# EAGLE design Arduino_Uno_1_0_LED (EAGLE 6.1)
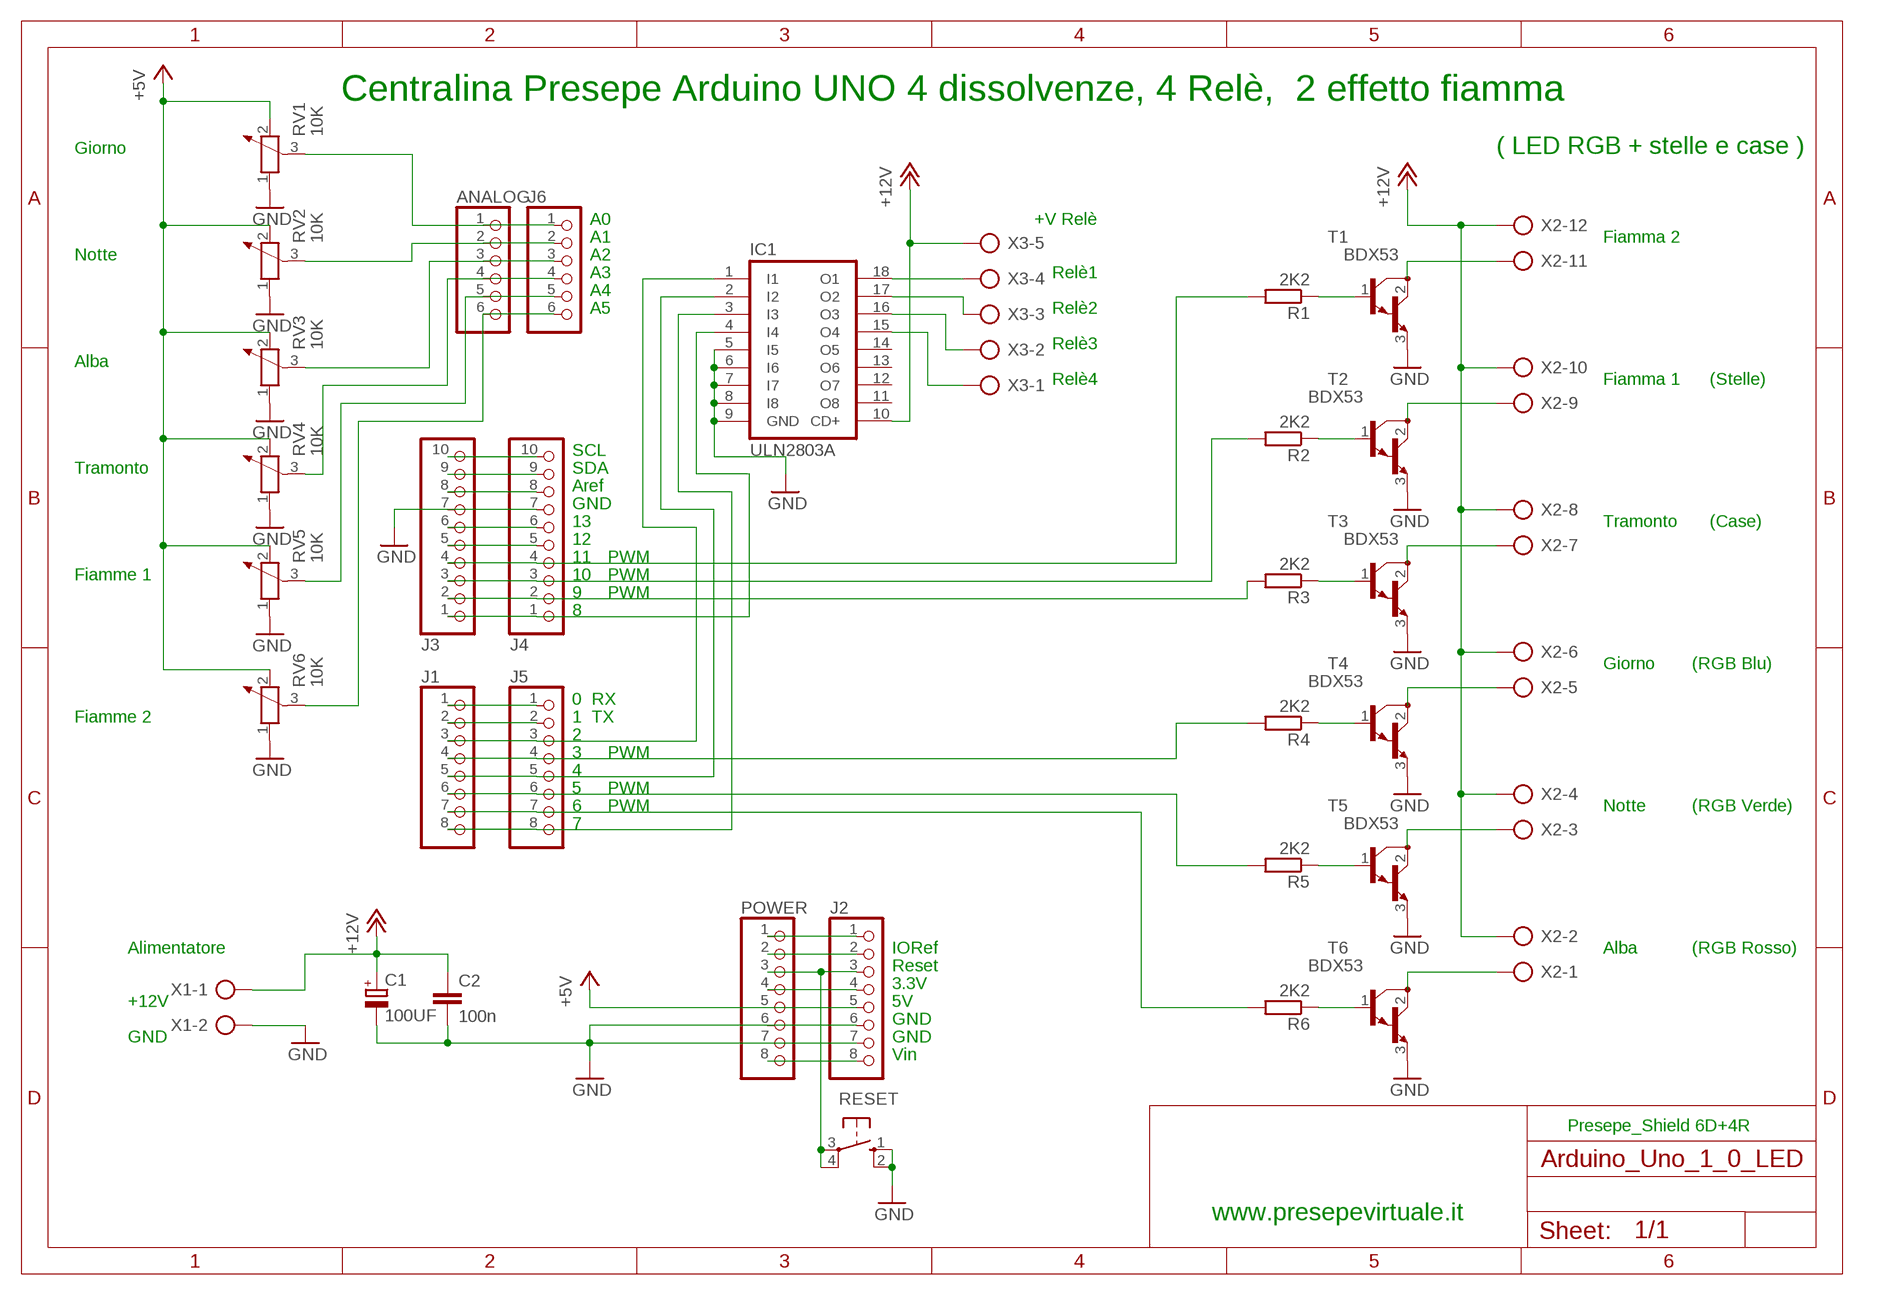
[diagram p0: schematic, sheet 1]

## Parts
ANALOG  PINHD-1X6  [1X06]
C1  100UF  CPOL-EUE5-4  [E5-4]
C2  100n  C-EU050-024X044  [C050-024X044]
IC1  ULN2803A  [DIL18]
J1  PINHD-1X8TH  [1X08-TH]
J2  PINHD-1X8TH  [1X08-TH]
J3  PINHD-1X10TH  [1X10-TH]
J4  PINHD-1X10TH  [1X10-TH]
J5  PINHD-1X8TH  [1X08-TH]
J6  PINHD-1X6  [1X06]
POWER  PINHD-1X8TH  [1X08-TH]
R1  2K2  R-EU_0207/5V  [0207/5V]
R2  2K2  R-EU_0207/5V  [0207/5V]
R3  2K2  R-EU_0207/5V  [0207/5V]
R4  2K2  R-EU_0207/5V  [0207/5V]
R5  2K2  R-EU_0207/5V  [0207/5V]
R6  2K2  R-EU_0207/5V  [0207/5V]
RESET  10-XX  [B3F-10XX]
RV1  10K  POTENTIOMETER_PT-10S  [PT-10S]
RV2  10K  POTENTIOMETER_PT-10S  [PT-10S]
RV3  10K  POTENTIOMETER_PT-10S  [PT-10S]
RV4  10K  POTENTIOMETER_PT-10S  [PT-10S]
RV5  10K  POTENTIOMETER_PT-10S  [PT-10S]
RV6  10K  POTENTIOMETER_PT-10S  [PT-10S]
T1  BDX53  [TO220]
T2  BDX53  [TO220]
T3  BDX53  [TO220]
T4  BDX53  [TO220]
T5  BDX53  [TO220]
T6  BDX53  [TO220]
X1  AK500/2  [AK500/2]
X2  AK500/12  [AK500/12]
X3  AK500/5  [AK500/5]

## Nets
+5V: J2.5 POWER.5 RV1.2 RV2.2 RV3.2 RV4.2 RV5.2 RV6.2
+9V: J2.8 POWER.8
+12V: C1.+ C2.1 IC1.10(CD+) X1.1 X2.2 X2.4 X2.6 X2.8 X2.10 X2.12 X3.5
GND: C1.- C2.2 IC1.5(I5) IC1.6(I6) IC1.7(I7) IC1.8(I8) IC1.9(GND) J2.6 J2.7 J3.7 J4.7 POWER.6 POWER.7 RESET.1(S) RESET.2(S1) RV1.1 RV2.1 RV3.1 RV4.1 RV5.1 RV6.1 T1.3(E) T2.3(E) T3.3(E) T4.3(E) T5.3(E) T6.3(E) X1.2
N$1: J3.5 J4.5
N$2: IC1.4(I4) J3.1 J4.1
N$3: J3.6 J4.6
N$4: R3.1 T3.1(B)
N$5: J3.4 J4.4 R1.2
N$6: J3.2 J4.2 R3.2
N$7: J3.3 J4.3 R2.2
N$8: J1.1 J5.1
N$9: J1.2 J5.2
N$10: IC1.1(I1) J1.3 J5.3
N$11: J1.4 J5.4 R4.2
N$12: R4.1 T4.1(B)
N$13: J1.6 J5.6 R5.2
N$14: J1.7 J5.7 R6.2
N$15: IC1.3(I3) J1.8 J5.8
N$16: T4.2(C) X2.5
N$17: R5.1 T5.1(B)
N$18: R6.1 T6.1(B)
N$19: ANALOG.2 J6.2 RV2.3
N$20: ANALOG.3 J6.3 RV3.3
N$21: ANALOG.4 J6.4 RV4.3
N$22: ANALOG.5 J6.5 RV5.3
N$23: ANALOG.6 J6.6 RV6.3
N$24: T6.2(C) X2.1
N$25: T5.2(C) X2.3
N$26: T3.2(C) X2.7
N$27: T1.2(C) X2.11
N$30: IC1.18(O1) X3.4
N$31: J2.2 POWER.2
N$32: J2.1 POWER.1
N$33: IC1.17(O2) X3.3
N$34: ANALOG.1 J6.1 RV1.3
N$43: IC1.16(O3) X3.2
N$44: IC1.15(O4) X3.1
N$49: R1.1 T1.1(B)
N$50: R2.1 T2.1(B)
N$52: T2.2(C) X2.9
N$54: IC1.2(I2) J1.5 J5.5
N$141: J3.9 J4.9
N$142: J3.10 J4.10
N$222: J3.8 J4.8
N$223: J2.4 POWER.4
RESET: J2.3 POWER.3 RESET.3(P) RESET.4(P1)
Unconnected: IC1.11(O8) IC1.12(O7) IC1.13(O6) IC1.14(O5)

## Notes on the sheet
- Centralina Presepe Arduino UNO 4 dissolvenze, 4 Relè,  2 effetto fiamma
- Giorno | ( LED RGB + stelle e case )
- A0 | +V Relè
- A1 | Fiamma 2
- Notte | A2
- A3 | Relè1
- A4
- A5 | Relè2
- Relè3
- Alba
- Relè4 | Fiamma 1 | (Stelle)
- SCL
- Tramonto | SDA
- Aref
- GND
- 13 | Tramonto | (Case)
- 12
- 11 | PWM
- Fiamme 1 | 10 | PWM
- 9 | PWM
- 8
- Giorno | (RGB Blu)
- 0  RX
- Fiamme 2 | 1  TX
- 2
- 3 | PWM
- 4
- 5 | PWM
- 6 | PWM | Notte | (RGB Verde)
- 7
- Alimentatore | IORef | Alba | (RGB Rosso)
- Reset
- 3.3V
- +12V | 5V
- GND
- GND | GND
- Vin
- Presepe_Shield 6D+4R
- www.presepevirtuale.it

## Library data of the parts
ANALOG J6 = pinhead:PINHD-1X6: PIN HEADER
C1 = rcl:CPOL-EU: POLARIZED CAPACITOR, European symbol
C2 = rcl:C-EU: CAPACITOR, European symbol
IC1 = uln-udn:ULN2803A: DRIVER ARRAY
J1 J2 J5 POWER = SmartPrj:PINHD-1X8: PIN HEADER
J3 J4 = SmartPrj:PINHD-1X10: PIN HEADER
R1-R6 = rcl:R-EU_: RESISTOR, European symbol
RESET = switch-omron:10-XX: OMRON SWITCH
RV1-RV6 = rcl:POTENTIOMETER_: Potentiometer
T1-T6 = transistor:BDX53: NPN BIPOLAR DARLINGTON TRANSISTOR
X1 = con-ptr500:AK500/2: CONNECTOR
X2 = con-ptr500:AK500/12: CONNECTOR
X3 = con-ptr500:AK500/5: CONNECTOR

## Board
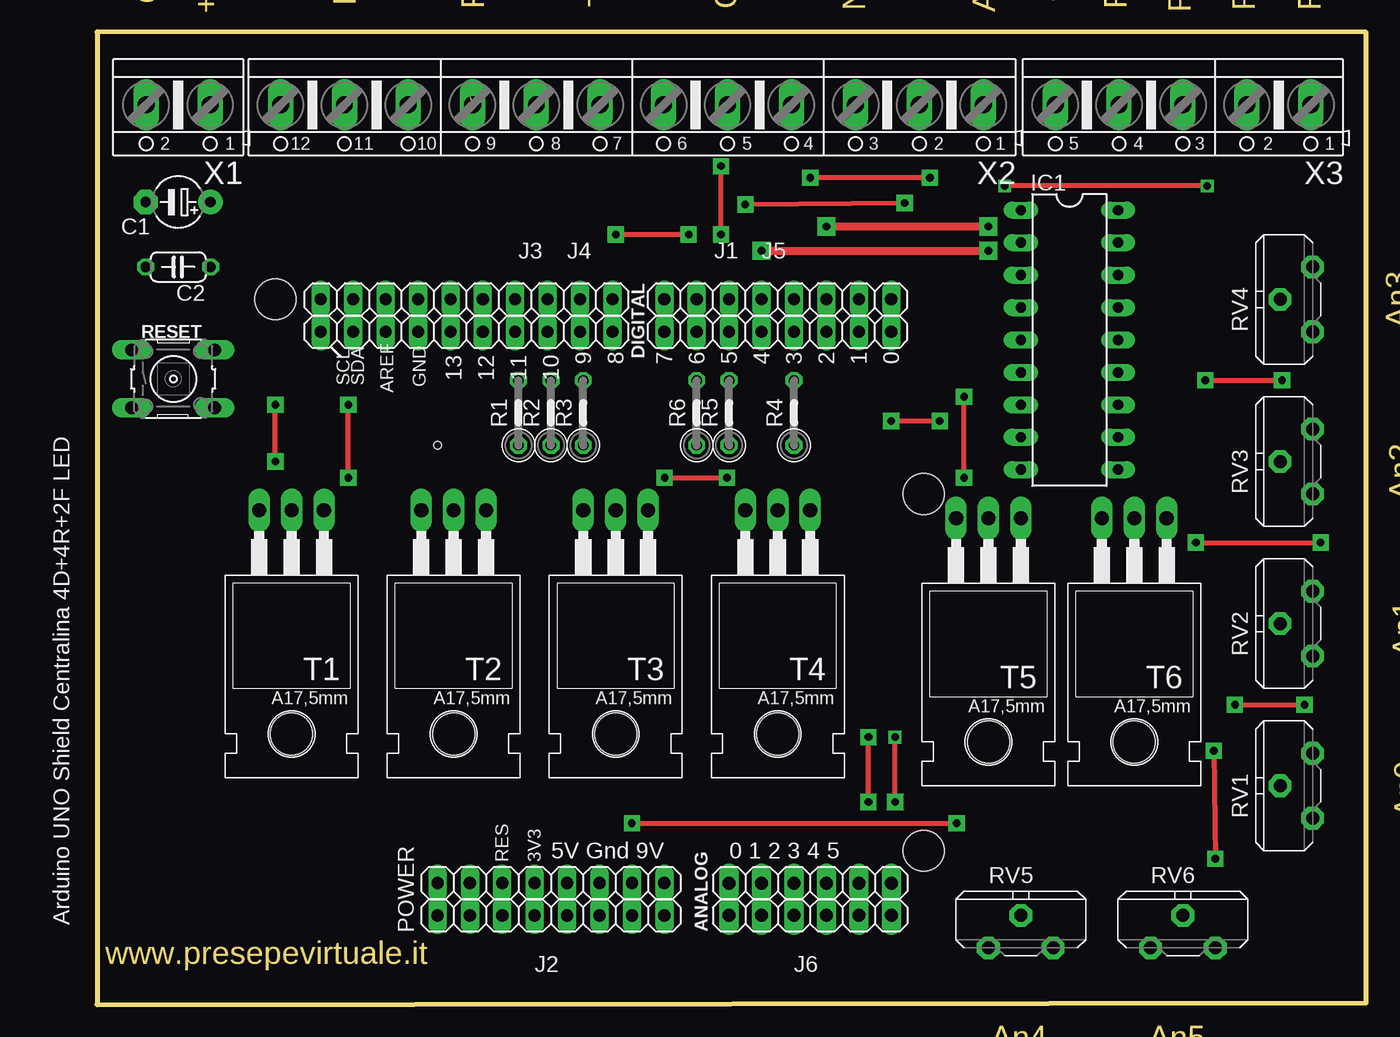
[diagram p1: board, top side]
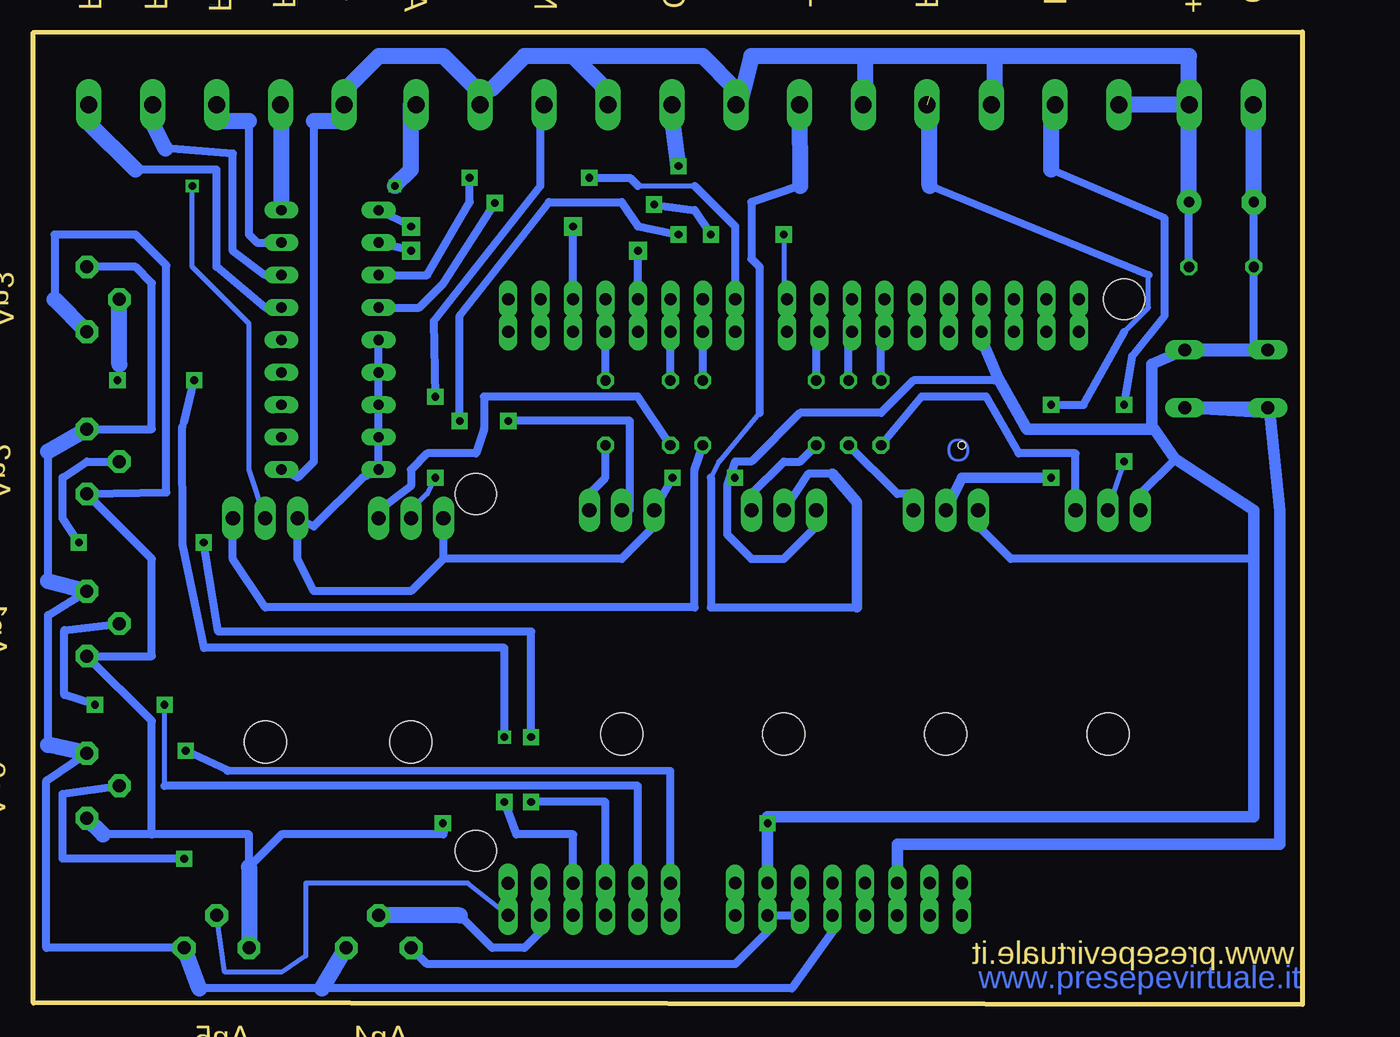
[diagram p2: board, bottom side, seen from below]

Size 99.46 x 76.2 mm. Coordinates in mm from the lower left corner, seen from the top.
Outline: 0,76.2 0,0 99.46,0.13 99.46,76.17 0,76.2
Copper layers (1*16): Top 0.035mm / dielectric 1.5mm / Bottom 0.035mm
Design rules "default *": minimum track width 24mil, minimum drill 20mil, track to track 24mil, track to pad 24mil, pad to pad 24mil, via to via 24mil, smd to smd 8mil, copper to edge 10mil, drill to drill 8mil, minimum pad ring 10mil, minimum via ring 8mil, stop-mask expansion 2mil, vias tented up to drill 0mil, thermal gap 10mil
Holes 3.2 mm at 13.97,55.24 64.77,12.07 64.77,40.01
Holes 0.6 mm at 26.67,43.81

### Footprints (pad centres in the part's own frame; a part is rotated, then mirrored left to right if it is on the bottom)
1X06 = drill 1.016 long: 1 -6.35,0; 2 -3.81,0; 3 -1.27,0; 4 1.27,0; 5 3.81,0; 6 6.35,0
E5-4 = drill 0.813 pad 1.905 round: + -2.54,0 | drill 0.813 pad 1.905 octagon: - 2.54,0
C050-024X044 = drill 0.813 octagon: 1 -2.54,0; 2 2.54,0
DIL18 = drill 0.813 long: 1 -10.16,-3.81; 2 -7.62,-3.81; 3 -5.08,-3.81; 4 -2.54,-3.81; 5 0,-3.81; 6 2.54,-3.81; 7 5.08,-3.81; 8 7.62,-3.81; 9 10.16,-3.81; 10 10.16,3.81; 11 7.62,3.81; 12 5.08,3.81; 13 2.54,3.81; 14 0,3.81; 15 -2.54,3.81; 16 -5.08,3.81; 17 -7.62,3.81; 18 -10.16,3.81
1X08-TH = drill 0.95 pad 1.422 long: 1 -8.89,0; 2 -6.35,0; 3 -3.81,0; 4 -1.27,0; 5 1.27,0; 6 3.81,0; 7 6.35,0; 8 8.89,0
1X10-TH = drill 0.95 pad 1.422 long: 1 -11.43,0; 2 -8.89,0; 3 -6.35,0; 4 -3.81,0; 5 -1.27,0; 6 1.27,0; 7 3.81,0; 8 6.35,0; 9 8.89,0; 10 11.43,0
0207/5V = drill 0.813 octagon: 1 -2.54,0; 2 2.54,0
B3F-10XX = drill 1.016 long: 1 -3.251,2.261; 2 3.251,2.261; 3 -3.251,-2.261; 4 3.251,-2.261
PT-10S = drill 1.016 pad 1.778 octagon: 1 -2.54,-1.27; 2 2.54,-1.27; 3 0,1.27
TO220 = drill 1.118 long: 1 -2.54,-6.35; 2 0,-6.35; 3 2.54,-6.35 | hole 3.302: 0,11.176
AK500/2 = drill 1.321 long: 1 -2.515,0; 2 2.515,0
AK500/12 = drill 1.321 long: 1 -27.534,0; 2 -22.53,0; 3 -17.526,0; 4 -12.497,0; 5 -7.493,0; 6 -2.489,0; 7 2.489,0; 8 7.493,0; 9 12.497,0; 10 17.526,0; 11 22.53,0; 12 27.534,0
AK500/5 = drill 1.321 long: 1 -10.033,0; 2 -5.004,0; 3 0,0; 4 5.004,0; 5 10.008,0

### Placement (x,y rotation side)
ANALOG  55.88,6.99 0 top
C1  6.35,62.87 180 top
C2  6.35,57.79 180 top
IC1  76.2,52.07 270 top
J1  53.34,55.24 180 top
J2  35.56,6.99 0 top
J3  28.96,55.24 180 top
J4  28.96,52.7 180 top
J5  53.34,52.7 180 top
J6  55.88,9.53 0 top
POWER  35.56,9.53 0 top
R1  33.02,46.35 90 top
R2  35.56,46.35 90 top
R3  38.1,46.35 90 top
R4  54.61,46.35 90 top
R5  49.53,46.35 90 top
R6  46.99,46.35 90 top
RESET  5.97,49.02 0 top
RV1  93.98,17.14 90 top
RV2  93.98,29.84 90 top
RV3  93.98,42.55 90 top
RV4  93.98,55.24 90 top
RV5  72.39,5.71 0 top
RV6  85.09,5.71 0 top
T1  15.24,32.39 180 top
T2  27.94,32.39 180 top
T3  40.64,32.39 180 top
T4  53.34,32.39 180 top
T5  69.85,31.75 180 top
T6  81.28,31.75 180 top
X1  6.35,70.49 180 top
X2  41.91,70.49 180 top
X3  85.09,70.49 180 top

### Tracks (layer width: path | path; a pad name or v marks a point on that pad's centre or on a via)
+5V
  Bottom 0.61: POWER.5 J2.5 36.83,5.71 40,1.27 76.84,1.27 86.44,1.27 | RV1.2 98.43,17.54 98.43,4.44 RV6.2 | RV2.2 98.29,30.51 98.29,20.35 | 98.29,33.18 98.29,43.34 | RV4.2 91.44,57.79 90.17,56.52 90.17,45.09 RV3.2
  Bottom 1.27: 76.84,1.27 RV5.2 | 86.44,1.27 RV6.2 | RV1.2 98.29,20.35 | 98.29,43.34 RV3.2 | RV2.2 98.29,33.18
+9V
  Bottom 0.61: J2.8 POWER.8
+12V
  Bottom 0.61: C2.1 C1.+ | 24.13,69.22 X2.10 | 34.29,69.22 X2.8 | 44.45,69.22 X2.6 44.45,71.75 | 8.89,69.22 X1.1 | 54.61,71.75 X2.4 | 63.5,71.75 X2.2 64.77,71.75 | 77.47,69.22 77.47,42.55 78.74,41.27 IC1.10 | 74.93,69.22 X3.5 74.93,71.75
  Bottom 1.27: X1.1 X2.12 | 24.13,74.29 8.89,74.29 C1.+ 8.89,69.22 | 24.13,74.29 24.13,69.22 | 34.29,74.29 34.29,69.22 | 24.13,74.29 34.29,74.29 | 44.45,69.22 43.18,74.29 34.29,74.29 | 57.15,74.29 54.61,71.75 | 57.15,74.29 60.96,74.29 63.5,71.75 | 74.93,69.22 77.47,69.22 | 64.77,71.75 67.31,74.29 72.39,74.29 74.93,71.75 | 44.45,71.75 46.99,74.29 57.15,74.29
GND  (via drill 0.6 pad 1.27)
  Top 0.406: v41.91,14.21 v67.36,14.21 | v44.47,41.27 v49.36,41.27
  Bottom 0.406: 45.08,40.64 v44.47,41.27
  Bottom 0.61: J4.7 J3.7 | POWER.7 J2.7 | POWER.6 J2.6 J2.7 | 90.17,13.34 93.98,13.34 | 90.17,13.34 82.55,13.34 82.55,10.79 80.01,13.34 67.31,13.34 v67.36,14.21 | 90.17,13.34 90.17,22.23 RV2.1 90.17,27.3 90.17,34.92 RV3.1 89.03,40.14 89.03,57.92 91.44,60.33 97.79,60.33 97.79,55.24 | IC1.5 IC1.6 IC1.7 IC1.8 IC1.9 73.66,41.27 77.47,37.47 T6.3 78.74,34.92 77.47,32.39 69.85,32.39 67.31,34.92 | 67.31,34.92 53.34,34.92 50.8,37.47 T4.3 v49.36,41.27 | 67.31,34.92 T5.3 | C1.- C2.2 3.81,51.44 RESET.1 | 3.81,69.22 X1.2 | T1.3 12.7,40.01 10.16,42.55 10.01,42.77 | 3.81,34.92 22.86,34.92 25.4,37.47 T2.3 | T3.3 38.1,37.47 40.64,34.92 43.18,34.92 45.08,36.83 45.08,40.64 44.45,42.55 43.18,42.55 39.37,46.35 33.02,46.35 30.48,48.9 24.13,48.9 23.82,49.03 | RV5.1 68.58,3.18 44.45,3.18 41.91,5.71 J2.7
  Bottom 0.889: 11.59,45.07 10.01,42.77 3.81,38.73 3.81,34.92 3.81,14.73 41.91,14.73 v41.91,14.21 POWER.7 | RESET.2 11.8,50.16 11.8,45.09 11.59,45.07 | 11.59,45.07 21.59,45.09 23.82,49.03 25.4,52.7 J4.7
  Bottom 1.016: RESET.2 RESET.1
  Bottom 1.27: 82.55,10.79 RV6.1 | 93.98,13.34 RV1.1 | 97.79,55.24 RV4.1 | C1.- 3.81,69.22
N$1
  Bottom 0.61: J4.5 J3.5
N$2  (via drill 0.6 pad 1.27)
  Top 0.406: v63.28,62.79 v50.8,62.68 | v46.35,60.33 v40.64,60.33
  Bottom 0.406: J3.1 40.64,55.24 v40.64,60.33
  Bottom 0.61: J4.1 J3.1 | IC1.4 69.22,54.61 67.31,56.52 v63.28,62.79 | v50.8,62.68 47.62,62.23 v46.35,60.33
N$3
  Bottom 0.61: J4.6 J3.6
N$4
  Bottom 0.61: R3.1 39.37,42.55 40.64,42.55 43.18,40.01 T3.1
N$5
  Bottom 0.61: J3.4 J4.4 33.02,51.44 R1.2
N$6
  Bottom 0.61: J3.2 J4.2 38.1,51.44 R3.2
N$7
  Bottom 0.61: J3.3 J4.3 35.56,51.44 R2.2
N$8
  Bottom 0.61: J5.1 J1.1
N$9
  Bottom 0.61: J5.2 J1.2
N$10  (via drill 0.6 pad 1.42)
  Top 0.61: v57.15,60.96 v69.85,60.96
  Bottom 0.61: J5.3 J1.3 v57.15,60.96 | v69.85,60.96 IC1.1
N$11
  Bottom 0.61: J1.4 J5.4 R4.2
N$12
  Bottom 0.61: R4.1 54.61,41.27 55.88,40.01 T4.1
N$13
  Bottom 0.61: J1.6 J5.6 R5.2
N$14
  Bottom 0.61: J1.7 J5.7 R6.2
N$15  (via drill 0.6 pad 1.27)
  Top 0.406: v65.26,64.77 v55.88,64.77
  Bottom 0.406: 52.07,64.13 47.62,64.13
  Bottom 0.61: J5.8 J1.8 44.45,60.96 47.62,64.13 | IC1.3 68.58,57.15 65.26,62.87 v65.26,64.77 | v55.88,64.77 52.7,64.77 52.07,64.13
N$16  (via drill 0.6 pad 1.27)
  Top 0.406: v62.23,45.72 v66.04,45.72 | v48.89,60.33 v48.89,65.69
  Bottom 0.406: T4.2 52.7,38.73 | 49.53,70.49 X2.5
  Bottom 0.61: 52.7,38.73 52.7,45.72 v62.23,45.72 | v66.04,45.72 66.04,53.98 59.05,62.87 53.34,62.87 52.07,60.96 v48.89,60.33
  Bottom 1.27: v48.89,65.69 49.53,70.49
N$17
  Bottom 0.61: R5.1 52.07,47.62 64.14,47.62 64.14,45.09 64.77,43.18 68.58,43.18 69.85,41.91 69.85,40.64 72.39,38.73 T5.1
N$18
  Bottom 0.61: R6.1 47.62,41.91 47.62,31.12 81.28,31.12 83.82,34.92 T6.1
N$19  (via drill 0.6 pad 1.27)
  Top 0.406: v89.16,23.5 v94.62,23.5
  Bottom 0.406: 89.16,17.14 v89.16,23.5
  Bottom 0.61: ANALOG.2 J6.2 52.07,17.14 89.16,17.14 | v94.62,23.5 97.02,24.26 97.02,29.34 RV2.3
N$20  (via drill 0.6 pad 1.27)
  Top 0.406: v60.44,15.88 v60.44,20.96 | v86.11,36.2 v95.89,36.2
  Bottom 0.61: ANALOG.3 J6.3 54.61,15.88 v60.44,15.88 | v60.44,20.96 60.44,29.21 84.95,29.21 v86.11,36.2 | v95.89,36.2 97.16,38.1 97.16,41.27 95.25,42.55 RV3.3
N$21  (via drill 0.6, 0.6 pad 1.27)
  Top 0.406: v62.53,15.88 v62.53,20.96 | v86.84,48.92 v92.86,48.92
  Bottom 0.406: 87.78,45.29 87.65,45.62 | v92.86,48.92 92.71,50.16
  Bottom 0.61: ANALOG.4 J6.4 57.15,13.34 61.59,13.34 v62.53,15.88 | v62.53,20.96 62.53,27.94 86.07,27.94 87.77,36.03 87.78,45.29 | 87.65,45.62 v86.84,48.92
  Bottom 1.27: 92.71,50.16 RV4.3
N$22
  Bottom 0.61: J6.5 ANALOG.5 59.69,5.71 60.96,4.45 63.5,4.45 66.04,6.99
  Bottom 1.27: 66.04,6.99 RV5.3
N$23
  Bottom 0.406: ANALOG.6 65.41,9.53 78.11,9.53 78.11,3.81 80.01,2.54 84.45,2.54 RV6.3
  Bottom 0.61: ANALOG.6 J6.6
N$24  (via drill 0.6)
  Top 0.406: v87,64.13 v71.12,64.13
  Bottom 0.406: T6.2 82.55,41.91 82.55,53.34 87,57.79 v87,64.13 | 69.85,70.49 X2.1
  Bottom 1.27: v71.12,64.13 69.85,65.41 69.85,70.49
N$25  (via drill 0.6 pad 1.27)
  Top 0.406: v67.95,41.27 v67.95,47.62
  Bottom 0.406: T5.2 69.85,38.73 68.58,40.01 v67.95,41.27 | 59.69,70.49 X2.3
  Bottom 0.61: v67.95,47.62 68.06,53.57 59.71,64.13 59.69,70.49
N$26
  Bottom 0.406: 42.54,46.35 45.72,42.55 46.35,41.27
  Bottom 0.61: 39.37,64.13 43.18,62.87 43.18,58.42 42.54,57.79 42.54,46.35 | 46.35,41.27 46.35,31.12 34.92,31.12 | 36.83,41.57 38.73,41.57 T3.2
  Bottom 0.813: 34.92,31.12 34.92,39.37 36.83,41.57
  Bottom 1.27: X2.7 39.37,64.13
N$27  (via drill 0.6 pad 1.27)
  Top 0.406: v13.97,42.55 v13.97,46.99
  Bottom 0.406: T1.2 v13.97,42.55 | 19.68,70.49 X2.11
  Bottom 0.61: v13.97,46.99 13.34,50.8 10.79,53.98 10.79,61.59 19.68,65.41
  Bottom 1.27: 19.68,65.41 19.68,70.49
N$30
  Bottom 0.61: 80.01,69.22 X3.4
  Bottom 1.27: IC1.18 80.01,69.22
N$31
  Bottom 0.61: J2.2 POWER.2
N$32
  Bottom 0.61: J2.1 POWER.1
N$33
  Bottom 0.61: 82.55,69.22 82.55,60.33 81.92,59.69 81.28,59.69 IC1.17 | 85.09,69.22 X3.3
  Bottom 1.27: 82.55,69.22 85.09,69.22
N$34  (via drill 0.6 pad 1.27)
  Top 0.406: v87.52,19.88 v87.63,11.43
  Bottom 0.61: ANALOG.1 J6.1 49.53,18.28 84.27,18.32 84.15,18.32 v87.52,19.88 | v87.63,11.43 97.16,11.43 97.16,16.51 RV1.3
N$43
  Bottom 0.61: 89.12,67.08 83.82,66.67 83.82,59.05 81.28,57.15 IC1.16
  Bottom 1.27: 89.12,67.08 90.17,69.22 X3.2
N$44
  Bottom 0.61: 91.44,65.41 85.09,65.41 85.09,57.79 81.28,54.61 IC1.15 | 95.25,69.22 X3.1
  Bottom 1.27: 91.44,65.41 95.25,69.22
N$49
  Bottom 0.61: R1.1 29.84,47.62 24.77,47.62 22.23,43.18 17.78,43.18 T1.1
N$50
  Bottom 0.61: R2.1 31.75,40.01 30.48,40.01 T2.1
N$52  (via drill 0.6 pad 1.27)  (1 unrouted)
  Top 0.406: v19.68,41.27 v19.68,46.99
  Bottom 0.406: 13.97,52.7 12.07,54.61 12.07,57.15
  Bottom 0.61: v19.68,46.99 17.14,46.99 13.97,52.7 | 12.07,57.15 29.21,64.13
  Bottom 0.813: T2.2 26.67,41.27 v19.68,41.27
  Bottom 1.27: 29.21,64.13 29.21,71.12
N$54  (via drill 0.6 pad 1.42)
  Top 0.61: v52.07,59.05 v69.85,59.05
  Bottom 0.61: J5.5 J1.5 v52.07,59.05 | v69.85,59.05 IC1.2
N$141
  Bottom 0.61: J4.9 J3.9
N$142
  Bottom 0.61: J4.10 J3.10
N$222
  Bottom 0.61: J4.8 J3.8
N$223
  Bottom 0.61: J2.4 POWER.4
RESET
  Bottom 0.61: POWER.3 J2.3
  Bottom 0.889: POWER.3 31.75,12.57 1.78,12.57 1.78,38.73 2.54,46.35 RESET.4
  Bottom 1.016: RESET.4 RESET.3

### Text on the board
Bottom: O | www.presepevirtuale.it
Dimension: +12V | +V | GND | Fiamma 2 | +V | Fiamma 1 (Stelle) | +V | Tramonto (Case) | +V | Giorno (RGB Blu) | +V | +V | +V | Relè 1 | Notte (RGB Verde) | Alba (RGB Rosso) | Relè 2 | Relè 3 | Relè 4 | An3 | An2 | An1 | An0 | www.presepevirtuale.it | An4 | An5
tPlace: 9 | 8 | 7 | 6 | 5 | 4 | 3 | 2 | 1 | 0 | 13 | 12 | 11 | 10 | Arduino UNO Shield Centralina 4D+4R+2F LED
tNames: DIGITAL | AREF | SCL | SDA | GND | RES | 3V3 | 5V Gnd 9V | 0 1 2 3 4 5
bStop: DIGITAL | SDA | AREF | SCL | GND | 13 | 12 | 11 | 9 | 8 | 7 | 6 | 5 | 4 | 3 | 2 | 1 | 0 | 10 | 14 | 8 | 1 | 7 | 1 | 2 | 3 | 4 | +5V | GND | . | 5 | 6 | IOREF | RST | 3.3V | 5V | GND | GND | VIN | ANALOG | 0 | 1 | 2 | 3 | 4 | 5
Reference: USB | ETH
